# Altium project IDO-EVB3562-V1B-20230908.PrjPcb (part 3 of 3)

## Sheet P21. USB3.SchDoc
size 420 x 297 mm
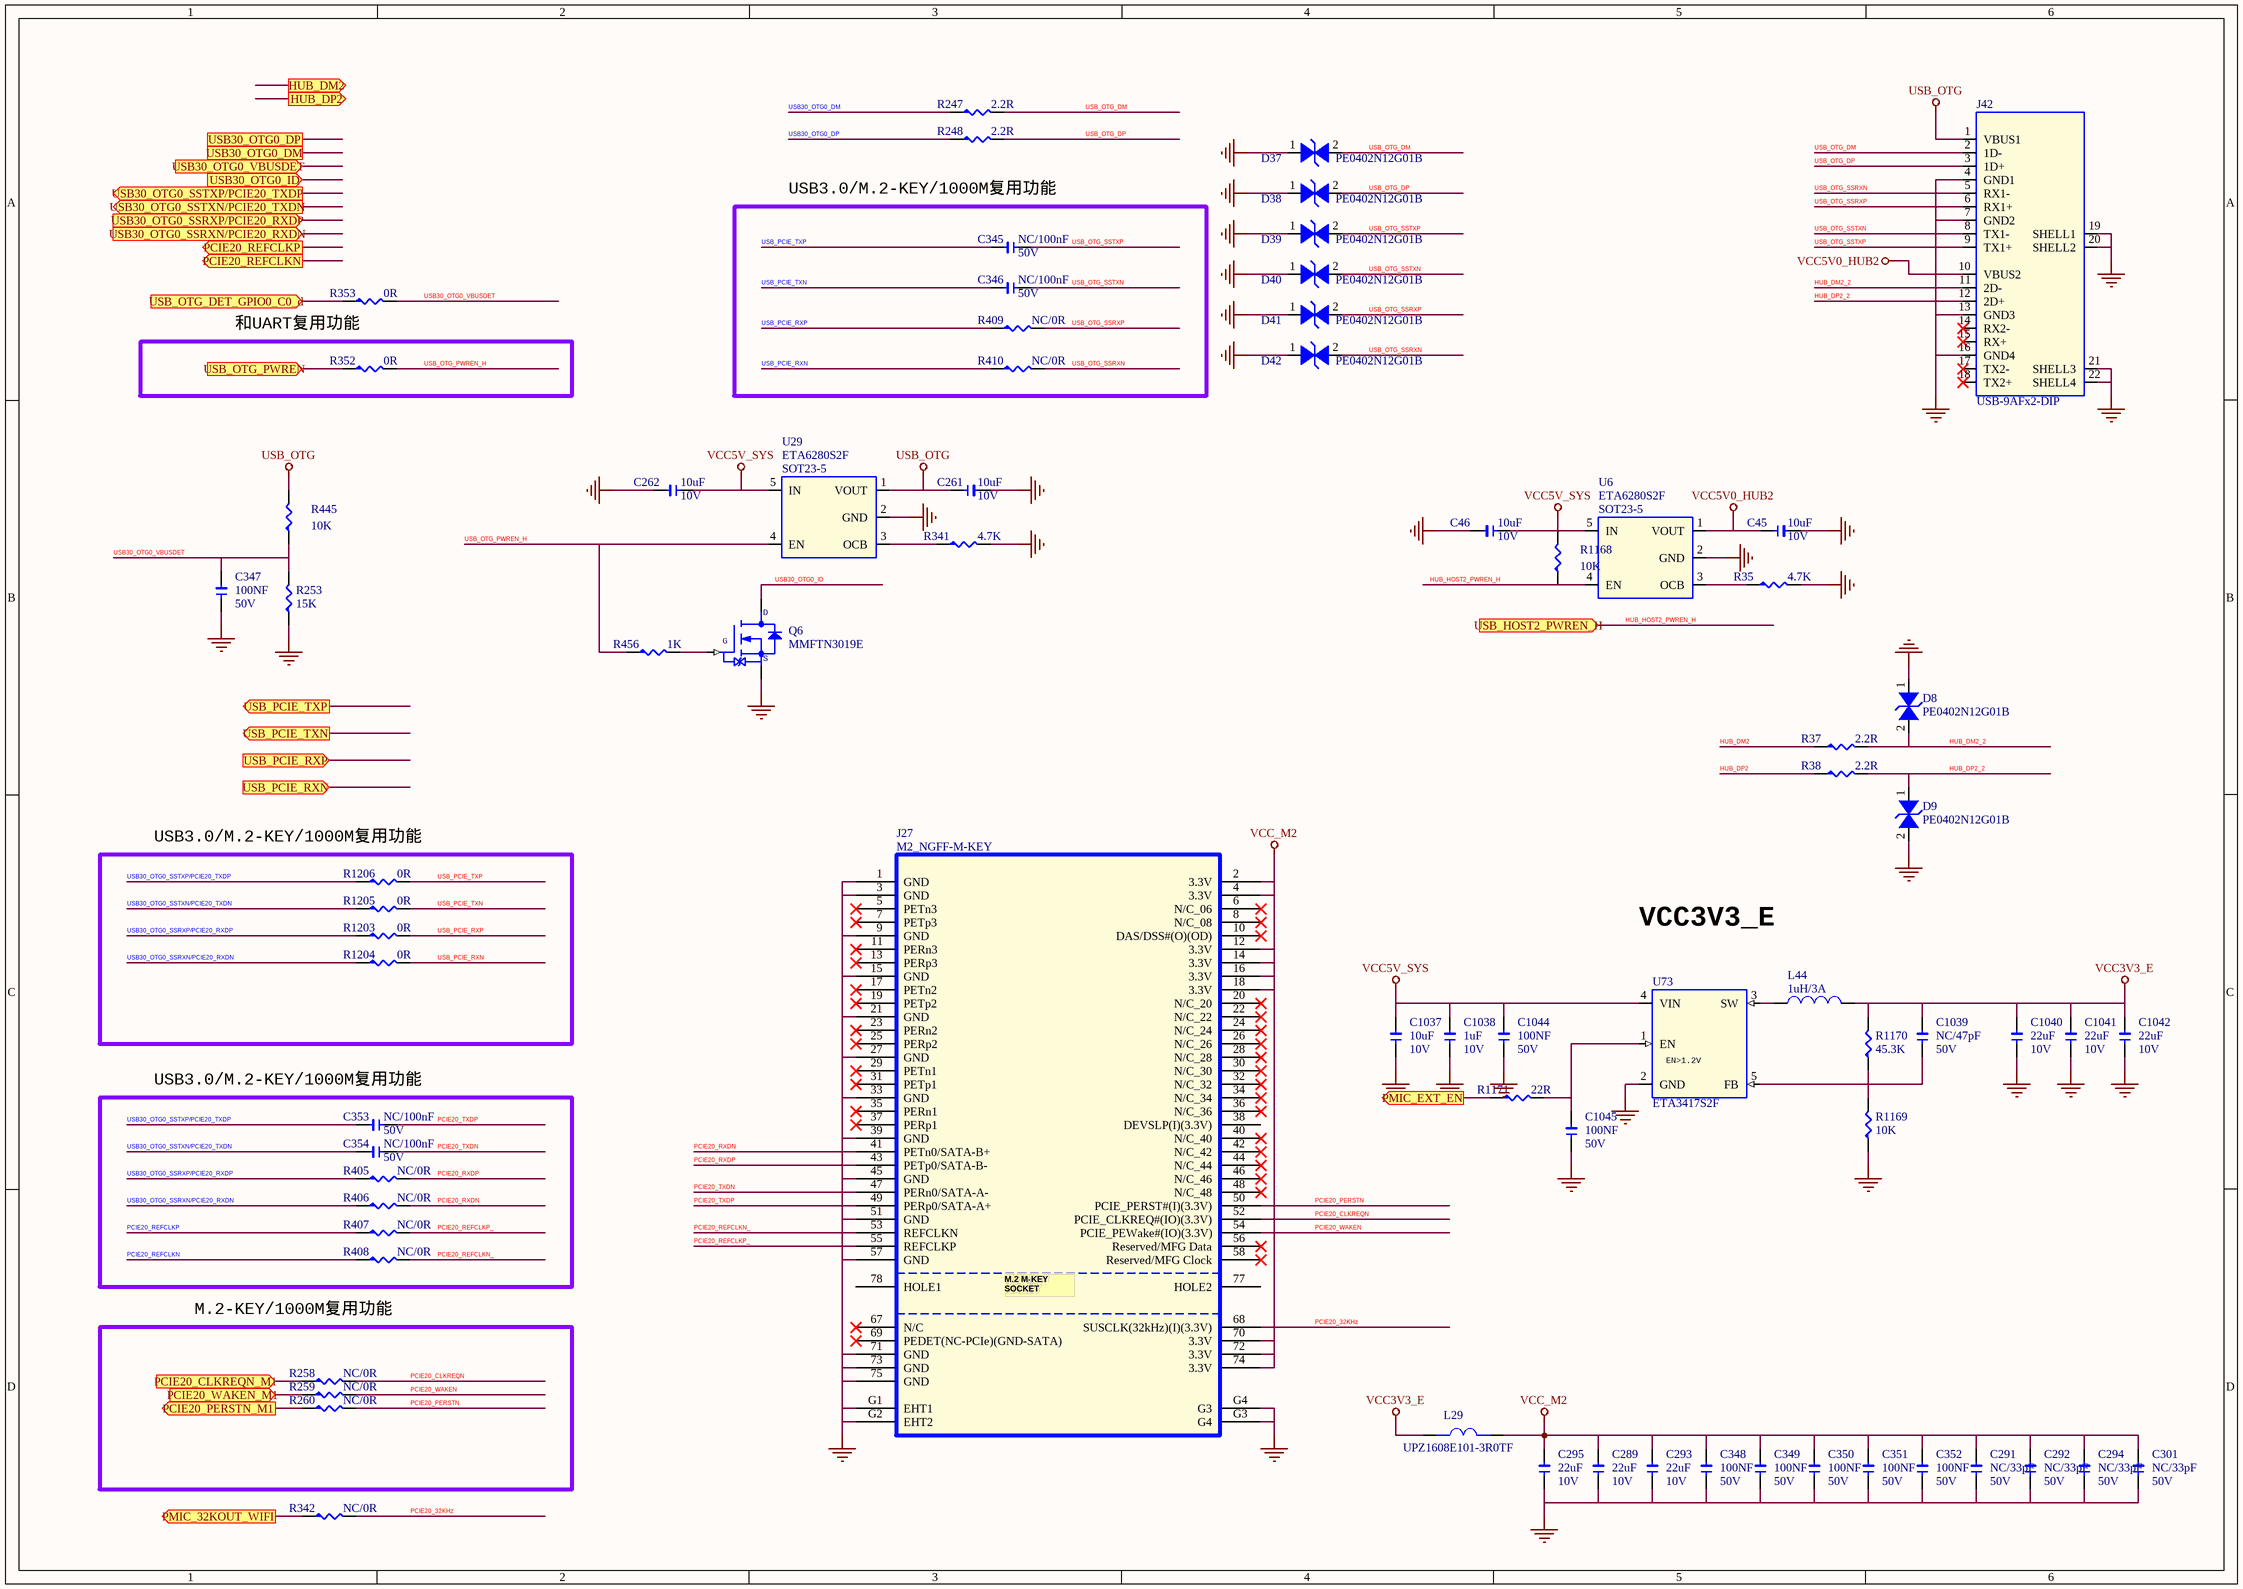
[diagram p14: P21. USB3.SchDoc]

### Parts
C45  10uF  DSC2: 10V  [1206]
C46  10uF  DSC2: 10V  [1206]
C261  10uF  DSC2: 10V  [1206]
C262  10uF  DSC2: 10V  [1206]
C289  22uF  DSC2: 10V  [1206]
C291  NC/33pF  DSC2: 50V  [1206]
C292  NC/33pF  DSC2: 50V  [1206]
C293  22uF  DSC2: 10V  [1206]
C294  NC/33pF  DSC2: 50V  [1206]
C295  22uF  DSC2: 10V  [1206]
C301  NC/33pF  DSC2: 50V  [1206]
C345  NC/100nF  DSC2: 50V  [1206]
C346  NC/100nF  DSC2: 50V  [1206]
C347  100NF  DSC2: 50V  [1206]
C348  100NF  DSC2: 50V  [1206]
C349  100NF  DSC2: 50V  [1206]
C350  100NF  DSC2: 50V  [1206]
C351  100NF  DSC2: 50V  [1206]
C352  100NF  DSC2: 50V  [1206]
C353  NC/100nF  DSC2: 50V  [1206]
C354  NC/100nF  DSC2: 50V  [1206]
C1037  10uF  DSC2: 10V  [1206]
C1038  1uF  DSC2: 10V  [1206]
C1039  NC/47pF  DSC2: 50V  [1206]
C1040  22uF  DSC2: 10V  [1206]
C1041  22uF  DSC2: 10V  [1206]
C1042  22uF  DSC2: 10V  [1206]
C1044  100NF  DSC2: 50V  [1206]
C1045  100NF  DSC2: 50V  [1206]
D8  PE0402N12G01B  [V0402]
D9  PE0402N12G01B  [V0402]
D37  PE0402N12G01B  [V0402]
D38  PE0402N12G01B  [V0402]
D39  PE0402N12G01B  [V0402]
D40  PE0402N12G01B  [V0402]
D41  PE0402N12G01B  [V0402]
D42  PE0402N12G01B  [V0402]
J27  M2_NGFF-M-KEY  [M2_NGFF-M-KEY]
J42  USB-9AFx2-DIP  [USB-9AF-DIP_2x]
L29  UPZ1608E101-3R0TF  [L0603]
L44  1uH/3A  [IND_252012]
Q6  MMFTN3019E  [SOT523]
R35  4.7K  [R0402]
R37  2.2R  [R0402]
R38  2.2R  [R0402]
R247  2.2R  [R0402]
R248  2.2R  [R0402]
R253  15K  [R0402]
R258  NC/0R  [R0402]
R259  NC/0R  [R0402]
R260  NC/0R  [R0402]
R341  4.7K  [R0402]
R342  NC/0R  [R0402]
R352  0R  [R0402]
R353  0R  [R0402]
R405  NC/0R  [R0402]
R406  NC/0R  [R0402]
R407  NC/0R  [R0402]
R408  NC/0R  [R0402]
R409  NC/0R  [R0402]
R410  NC/0R  [R0402]
R445  10K  [R0402]
R456  1K  [R0402]
R1168  10K  [R0402]
R1169  10K  [R0402]
R1170  45.3K  [R0402]
R1171  22R  [R0402]
R1203  0R  [R0402]
R1204  0R  [R0402]
R1205  0R  [R0402]
R1206  0R  [R0402]
U6  ETA6280S2F  [SOT23-5]
U29  ETA6280S2F  [SOT23-5]
U73  ETA3417S2F  [SOT23-5]

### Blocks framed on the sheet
USB3.0/M.2-KEY/1000M复用功能: C345 C346 R409 R410
和UART复用功能: R352
USB3.0/M.2-KEY/1000M复用功能: R1203-R1206
USB3.0/M.2-KEY/1000M复用功能: C353 C354 R405-R408
M.2-KEY/1000M复用功能: R258-R260

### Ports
HUB_DM2 (out), HUB_DP2 (out), PCIE20_CLKREQN_M1 (in), PCIE20_PERSTN_M1 (out), PCIE20_REFCLKN (out), PCIE20_REFCLKP (out), PCIE20_WAKEN_M1 (in), PMIC_32KOUT_WIFI (out), PMIC_EXT_EN (out), USB30_OTG0_DM, USB30_OTG0_DP, USB30_OTG0_ID (in), USB30_OTG0_SSRXN/PCIE20_RXDN (in), USB30_OTG0_SSRXP/PCIE20_RXDP (in), USB30_OTG0_SSTXN/PCIE20_TXDN (out), USB30_OTG0_SSTXP/PCIE20_TXDP (out), USB30_OTG0_VBUSDET (in), USB_HOST2_PWREN_H (in), USB_OTG_DET_GPIO0_C0_d (in), USB_OTG_PWREN (in), USB_PCIE_RXN (in), USB_PCIE_RXP (in), USB_PCIE_TXN (out), USB_PCIE_TXP (out)

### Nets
GND: C45.2 C46.2 C261.2 C262.2 C289.1 C291.1 C292.1 C293.1 C294.1 C295.1 C301.1 C347.1 C348.1 C349.1 C350.1 C351.1 C352.1 C1037.1 C1038.1 C1040.1 C1041.1 C1042.1 C1044.1 C1045.1 D8.1(I/O2) D9.2(I/O1) D37.1(I/O2) D38.1(I/O2) D39.1(I/O2) D40.1(I/O2) D41.1(I/O2) D42.1(I/O2) J27.1(GND) J27.3(GND) J27.9(GND) J27.15(GND) J27.21(GND) J27.27(GND) J27.33(GND) J27.39(GND) J27.45(GND) J27.51(GND) J27.57(GND) J27.71(GND) J27.73(GND) J27.75(GND) J27.G1(EHT1) J27.G2(EHT2) J27.G3(G4) J27.G4(G3) J42.4(GND1) J42.7(GND2) J42.13(GND3) J42.16(GND4) J42.19(SHELL1) J42.20(SHELL2) J42.21(SHELL3) J42.22(SHELL4) Q6.2(SOURCE) R35.2 R253.1 R341.2 R1169.1 U6.2(GND) U29.2(GND) U73.2(GND)
USB_OTG: C261.1 J42.1(VBUS1) R445.2 U29.1(VOUT)
VCC3V3_E: C1039.2 C1040.2 C1041.2 C1042.2 L29.1 L44.2 R1170.2
VCC5V0_HUB2: C45.1 J42.10(VBUS2) U6.1(VOUT)
VCC5V_SYS: C46.1 C262.1 C1037.2 C1038.2 C1044.2 R1168.2 U6.5(IN) U29.5(IN) U73.4(VIN)
VCC_M2: C289.2 C291.2 C292.2 C293.2 C294.2 C295.2 C301.2 C348.2 C349.2 C350.2 C351.2 C352.2 J27.2(3.3V) J27.4(3.3V) J27.12(3.3V) J27.14(3.3V) J27.16(3.3V) J27.18(3.3V) J27.70(3.3V) J27.72(3.3V) J27.74(3.3V) L29.2
HUB_DM2: R37.1
HUB_DM2_2: D8.2(I/O1) J42.11(2D-) R37.2
HUB_DP2: R38.1
HUB_DP2_2: D9.1(I/O2) J42.12(2D+) R38.2
HUB_HOST2_PWREN_H: R1168.1 U6.4(EN) ; port USB_HOST2_PWREN_H
PCIE20_32KHz: J27.68(SUSCLK(32kHz)(I)(3.3V)) R342.2
PCIE20_CLKREQN: J27.52(PCIE_CLKREQ#(IO)(3.3V)) R258.2
PCIE20_PERSTN: J27.50(PCIE_PERST#(I)(3.3V)) R260.2
PCIE20_REFCLKN: R408.1
PCIE20_REFCLKN_: J27.53(REFCLKN) R408.2
PCIE20_REFCLKP: R407.1
PCIE20_REFCLKP_: J27.55(REFCLKP) R407.2
PCIE20_RXDN: J27.41(PETn0/SATA-B+) R406.2
PCIE20_RXDP: J27.43(PETp0/SATA-B-) R405.2
PCIE20_TXDN: C354.1 J27.47(PERn0/SATA-A-)
PCIE20_TXDP: C353.1 J27.49(PERp0/SATA-A+)
PCIE20_WAKEN: J27.54(PCIE_PEWake#(IO)(3.3V)) R259.2
USB30_OTG0_DM: R247.1
USB30_OTG0_DP: R248.1
USB30_OTG0_ID: Q6.3(DRAIN)
USB30_OTG0_SSRXN/PCIE20_RXDN: R406.1 R1204.1
USB30_OTG0_SSRXP/PCIE20_RXDP: R405.1 R1203.1
USB30_OTG0_SSTXN/PCIE20_TXDN: C354.2 R1205.1
USB30_OTG0_SSTXP/PCIE20_TXDP: C353.2 R1206.1
USB30_OTG0_VBUSDET: C347.2 R253.2 R353.2 R445.1
USB_OTG_DM: D37.2(I/O1) J42.2(1D-) R247.2
USB_OTG_DP: D38.2(I/O1) J42.3(1D+) R248.2
USB_OTG_PWREN_H: R352.2 R456.1 U29.4(EN)
USB_OTG_SSRXN: D42.2(I/O1) J42.5(RX1-) R410.2
USB_OTG_SSRXP: D41.2(I/O1) J42.6(RX1+) R409.2
USB_OTG_SSTXN: C346.1 D40.2(I/O1) J42.8(TX1-)
USB_OTG_SSTXP: C345.1 D39.2(I/O1) J42.9(TX1+)
USB_PCIE_RXN: R410.1 R1204.2
USB_PCIE_RXP: R409.1 R1203.2
USB_PCIE_TXN: C346.2 R1205.2
USB_PCIE_TXP: C345.2 R1206.2
NetC1039_1: C1039.1 R1169.2 R1170.1 U73.5(FB)
NetC1045_2: C1045.2 R1171.2 U73.1(EN)
NetL44_1: L44.1 U73.3(SW)
NetM1_8: R1171.1 ; port PMIC_EXT_EN
NetM1_16: R342.1 ; port PMIC_32KOUT_WIFI
NetM1_72: R258.1 ; port PCIE20_CLKREQN_M1
NetM1_73: R259.1 ; port PCIE20_WAKEN_M1
NetM1_74: R260.1 ; port PCIE20_PERSTN_M1
NetM1_158: R353.1 ; port USB_OTG_DET_GPIO0_C0_d
NetQ6_1: Q6.1(GATE) R456.2
NetR35_1: R35.1 U6.3(OCB)
NetR341_1: R341.1 U29.3(OCB)
NetR352_1: R352.1 ; port USB_OTG_PWREN

Not connected (* = marked no-connect by the designer): J27 5(PETn3)* 6(N/C_06)* 7(PETp3)* 8(N/C_08)* 10(DAS/DSS#(O)(OD))* 11(PERn3)* 13(PERp3)* 17(PETn2)* 19(PETp2)* 20(N/C_20)* 22(N/C_22)* 23(PERn2)* 24(N/C_24)* 25(PERp2)* 26(N/C_26)* 28(N/C_28)* 29(PETn1)* 30(N/C_30)* 31(PETp1)* 32(N/C_32)* 34(N/C_34)* 35(PERn1)* 36(N/C_36)* 37(PERp1)* 38(DEVSLP(I)(3.3V)) 40(N/C_40)* 42(N/C_42)* 44(N/C_44)* 46(N/C_46)* 48(N/C_48)* 56(Reserved/MFG_Data)* 58(Reserved/MFG_Clock)* 67(N/C)* 69(PEDET(NC-PCIe)(GND-SATA))* 77(HOLE2) 78(HOLE1); J42 14(RX2-)* 15(RX+)* 17(TX2-)* 18(TX2+)*

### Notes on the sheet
- VCC3V3_E
- (near U73) EN>1.2V

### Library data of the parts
C45 = C-0603: Manufacture: 三星¦国巨¦村田; Part Name: 贴片电容; Part Number: C020102120071; PCB Footprint: C0603; ID: 71; DSC3: X5R; DSC1: ±20%; ERP Number: 1010200076
C46 = C-0603: Part Number: C020102120071; Part Name: 贴片电容; Manufacture: 三星¦国巨¦村田; ERP Number: 1010200076; DSC1: ±20%; DSC3: X5R; ID: 71; PCB Footprint: C0603
C261 = C-0603: Part Number: C020102120071; Part Name: 贴片电容; Manufacture: 三星¦国巨¦村田; PCB Footprint: C0603; ERP Number: 1010200076; DSC1: ±20%; DSC3: X5R; ID: 71
C262 C1037 = C-0603: Manufacture: 三星¦国巨¦村田; Part Name: 贴片电容; Part Number: C020102120071; ID: 71; DSC3: X5R; DSC1: ±20%; ERP Number: 1010200076; PCB Footprint: C0603
C289 C293 C295 = C-0603: Part Number: C020107143899; Part Name: 贴片电容; Manufacture: 三星¦国巨¦村田; PCB Footprint: C0603; DSC1: ±20%; DSC3: X5R; ID: 83
C291 C292 C294 C301 = C-0402_Dup1: Manufacture: 三星¦国巨¦村田; Part Name: 贴片电容; Part Number: C020102120033; ID: 33; DSC3: C0G; DSC1: ±5%; ERP Number: 1010200087; PCB Footprint: C0402
C345 C346 C353 = C-0402: Manufacture: 三星¦国巨¦村田; Part Name: 贴片电容; Part Number: C020102120061; ID: 61; DSC3: X7R; DSC1: ±10%; ERP Number: 1010200128; PCB Footprint: C0402
C347 C1044 C1045 = C-0402_Dup2: Part Number: C020102120061; Part Name: 贴片电容; Manufacture: 三星¦国巨¦村田; ERP Number: 1010200128; DSC1: ±10%; DSC3: X7R; ID: 61; PCB Footprint: C0402
C348-C352 = C-0402_Dup2: Manufacture: 三星¦国巨¦村田; Part Name: 贴片电容; Part Number: C020102120061; ID: 61; DSC3: X7R; DSC1: ±10%; ERP Number: 1010200128; PCB Footprint: C0402
C354 = C-0402: Part Number: C020102120061; Part Name: 贴片电容; Manufacture: 三星¦国巨¦村田; ERP Number: 1010200128; DSC1: ±10%; DSC3: X7R; ID: 61; PCB Footprint: C0402
C1038 = C-0402_Dup1: Part Number: C020102120064; Part Name: 贴片电容; Manufacture: 三星¦国巨¦村田; ERP Number: 1010200054; DSC1: ±10%; DSC3: X5R; ID: 64; PCB Footprint: C0402
C1039 = C-0402_Dup1: Part Number: C020102120036; Part Name: 贴片电容; Manufacture: 三星¦国巨¦村田; ERP Number: 1010200213; DSC1: ±5%; DSC3: C0G; ID: 36; PCB Footprint: C0402
C1040-C1042 = C-0603: Part Number: C020107143899; Part Name: 贴片电容; Manufacture: 三星¦国巨¦村田; DSC1: ±20%; DSC3: X5R; ID: 83; PCB Footprint: C0603
D8 = DI-ESD: ESD 0402; Part Number: C040504013980; Manufacture P/N: MLVG04021R0UV18; Manufacturer: INPAQ; Manufacture: 硕凯; PN Type: Varistor; DSC1: 双向; DSC2: Vdc=12V; DSC4: Vc=40V; DSC5: Cj=0.05pF; ID: 1; Solder: 推荐
D9 D37-D42 = DI-ESD: ESD 0402; Part Number: C040504013980; Manufacture P/N: MLVG04021R0UV18; Manufacturer: INPAQ; Manufacture: 硕凯; PN Type: Varistor; Solder: 推荐; ID: 1; DSC5: Cj=0.05pF; DSC4: Vc=40V; DSC2: Vdc=12V; DSC1: 双向
J27 = J-M2_NGFF-M-KEY_1: Part Number: J050105094667; Part Name: 金手指连接器; DSC1: M2_NGFF-M座子,0.5mm Pitch,H=4.2mm; DSC2: 67P; DSC3: 贴片; DSC4: 91302-42-067RDM(Umaxconn); ID: 28
J42 = J-USB-9AFx2-DIP-W: USB,TYPE-A,2PORT,R/A,W/SHIELD; Part Number: J060111093946; Part Name: USB连接器; VSTNO: H00025; DSC1: USB-3.0，插件弯脚，双层，蓝胶，有卷边，耐高温; DSC2: 17.5*14.5*15.5mm; DSC3: 通孔弯针; DSC5: JLX-USB-030（九龙熹）; ID: 14
L29 = FB-0603_Dup1: SMD Multilayer Ferrite Chip Bead,3A,30Ohm,0.03R; Manufacturer: SUNLORD; Manufacture2 P/N: PBY160808T-400Y-N; Manufacture P/N: PZ1608D300-3R0TF; Part Number: C060502370005; Part Name: 贴片磁珠; Manufacture: 顺络; PN Type: SMD FERRITE BEAD; ERP Number: 1010200207; DSC1: 100Ω@100MHz; DSC3: DCR=30mΩ; DSC4: 电源线; ID: 5
L44 = L-IND_Dup1: Manufacture: 宗成¦长江微电¦顺络; Part Name: 功率电感; ID: 52; DSC8: ZCRH252012-1uH-M(宗成); DSC7: FHD252012S-1R0MT(长江微电); DSC6: WPN252012H1R0MT(顺络); DSC5: 2.5*2.0*1.2mm; DSC4: 54mΩ; DSC3: Irms=3A; DSC2: Isat=3.6A; DSC1: ±20%
Q6 = N-MOS-Q: Part Number: C030202190004; Part Name: N-MOS; Manufacture: 先科; ERP Number: 1010800011; DSC1: Vds=30V; DSC2: Id=100mA; DSC3: Vgs(th)=1.5V; DSC4: Vgs=±20V; DSC5: pd=150mW; ID: 4
R35 R341 = R-0402_Dup3: Part Number: C011002080320; Part Name: 贴片电阻; ID: 320; DSC2: 1/16W; DSC1: ±5%; ERP Number: 1010200177
R37 R38 = R-0402_Dup3: Part Name: 贴片电阻; Part Number: C011002080238; ERP Number: 1010200263; DSC1: ±5%; DSC2: 1/16W; ID: 238
R247 R248 = R-0402_Dup3: Part Number: C011002080238; Part Name: 贴片电阻; ID: 238; DSC2: 1/16W; DSC1: ±5%; ERP Number: 1010200263
R253 = R-0402_Dup3: Part Name: 贴片电阻; Part Number: C011002080332; ERP Number: 1010200258; DSC1: ±5%; DSC2: 1/16W; ID: 332
R258-R260 R342 R353 R405-R410 R1203 R1205 R1206 = R-0402_Dup3: Part Number: C011002080413; Part Name: 贴片电阻; ID: 413; DSC2: 1/16W; DSC1: ±1%
R352 R1204 = R-0402_Dup3: Part Name: 贴片电阻; Part Number: C011002080413; DSC1: ±1%; DSC2: 1/16W; ID: 413
R445 R1168 R1169 = R-0402_Dup3: Part Number: C011002080856; Part Name: 贴片电阻; ID: 856; DSC2: 1/16W; DSC1: ±1%; ERP Number: 1010200140
R456 = R-0402_Dup3: Part Name: 贴片电阻; Part Number: C011002080742; ERP Number: 1010200113; DSC1: ±1%; DSC2: 1/16W; ID: 742
R1170 = R-0402_Dup3: Part Name: 贴片电阻; Part Number: C011002080933; DSC1: ±1%; DSC2: 1/16W; ID: 933
R1171 = R-0402_Dup3: Part Number: C011002080262; Part Name: 贴片电阻; ID: 262; DSC2: 1/16W; DSC1: ±5%; ERP Number: 1010200173
U6 = U-SY6280AAC: Part Name: 功率开关; Manufacture: ETA; DSC1: 低能耗电源开关; DSC2: 2.4-5.5V 2A; DSC3: 80mA; DSC4: -40~85℃; ID: 1
U29 = U-SY6280AAC: Manufacture: ETA; Part Name: 功率开关; ID: 1; DSC4: -40~85℃; DSC3: 80mA; DSC2: 2.4-5.5V 2A; DSC1: 低能耗电源开关
U73 = U-ETA3417S2F: Part Name: DCDC; Part Number: C070205183984; Manufacture: ETA; DSC1: Vi=2.6-7.0V; DSC2: Vo=0.6-7.0V; DSC3: Io=2.5A; DSC4: Vfb=0.6V; DSC6: 3MHz; DSC7: 同步降压; DSC8: 替代料：TI的TLV62569DBVR/矽力杰SY8089AAAC; Solder: 量产; ID: 43

## Sheet P22.SchDoc
size 297 x 209 mm
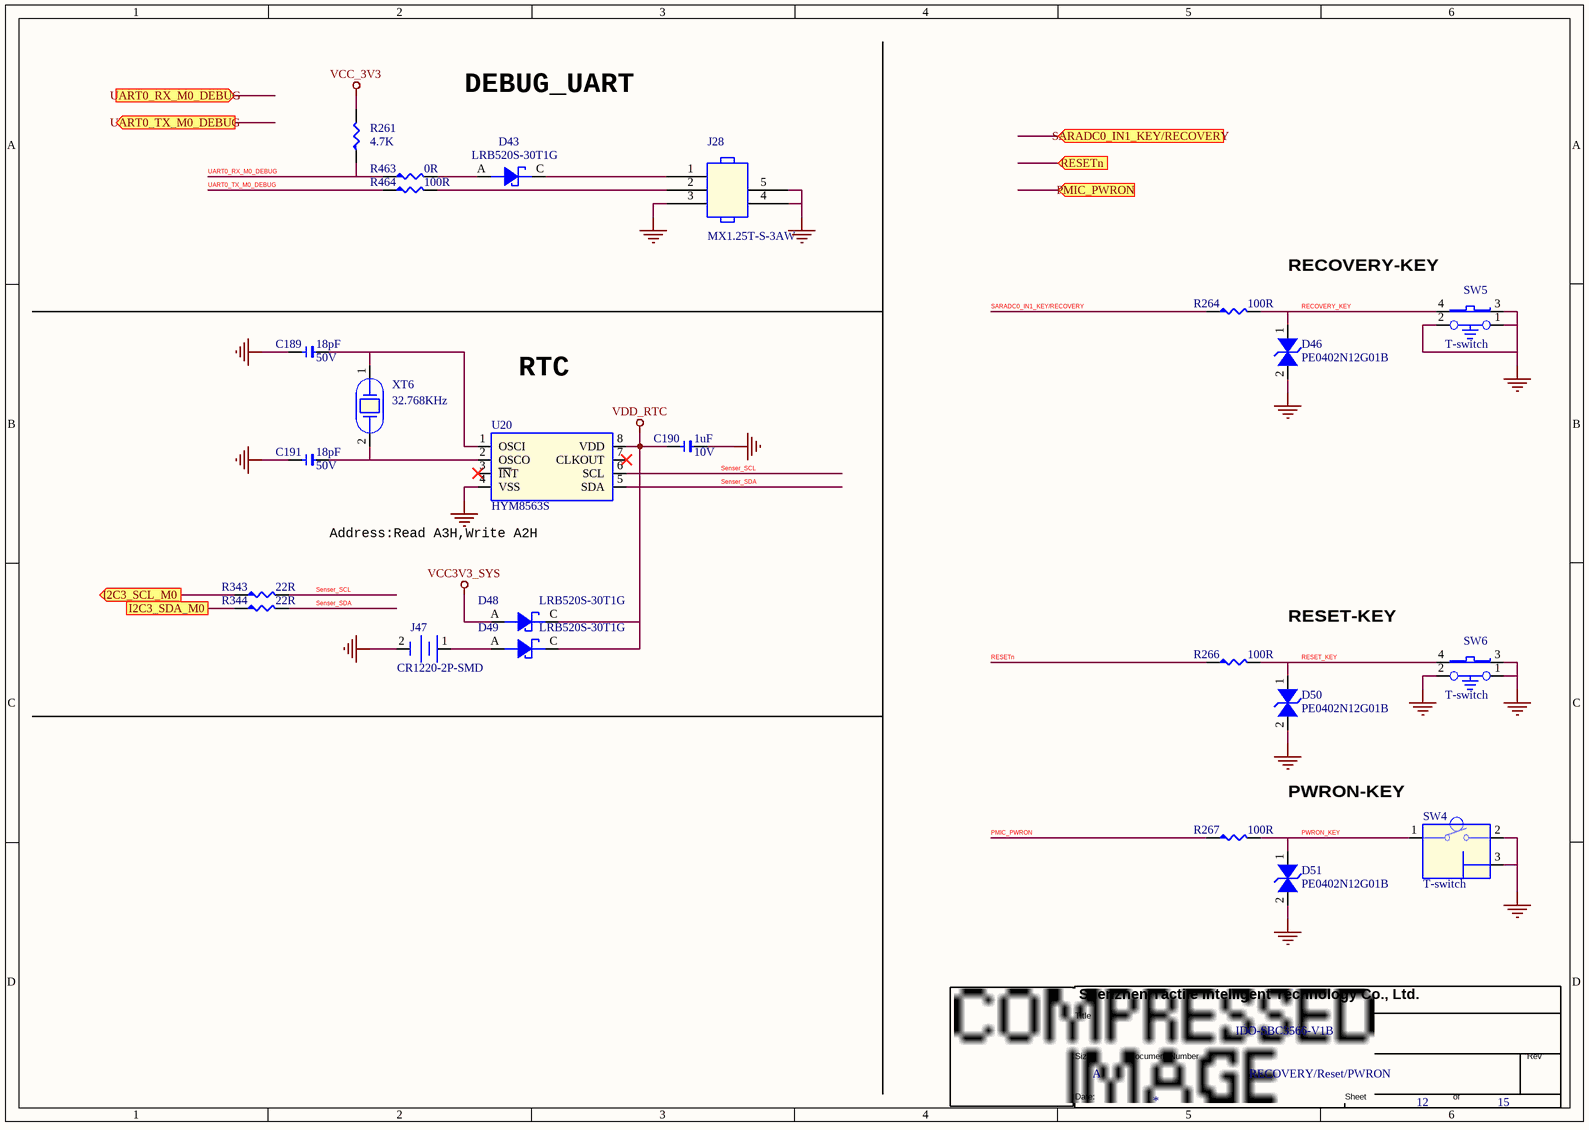
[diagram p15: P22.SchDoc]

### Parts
(Parts that share a designator on the sheet are numbered #1, #2 ... from top to bottom, then left to right.)
*#9  Page Count: 15  Page Number: 12  Page Size: A  Title: IDO-SBC3566-V1B  Doc: RECOVERY/Reset/PWRON  (hidden comment: TitleBlock1)  (graphical)
C189  18pF  DSC2: 50V  [1206]
C190  1uF  DSC2: 10V  [1206]
C191  18pF  DSC2: 50V  [1206]
D43  LRB520S-30T1G  [SOD523]
D46  PE0402N12G01B  [V0402]
D48  LRB520S-30T1G  [SOD523]
D49  LRB520S-30T1G  [SOD523]
D50  PE0402N12G01B  [V0402]
D51  PE0402N12G01B  [V0402]
J28  MX1.25T-S-3AW  [MX125T-S-3AW]
J47  CR1220-2P-SMD  [CR1220-2P-SMD]
R261  4.7K  [R0402]
R264  100R  [R0402]
R266  100R  [R0402]
R267  100R  [R0402]
R343  22R  [R0402]
R344  22R  [R0402]
R463  0R  [R0402]
R464  100R  [R0402]
SW4  T-switch  [PB-SIDE-P-4_5x4_5]
SW5  T-switch  [PB-SIDE-S-3_5x4_5]
SW6  T-switch  [PB-SIDE-S-3_5x4_5]
U20  HYM8563S  [MSOP-8]
XT6  32.768KHz  [XTAL_32X15_2P]

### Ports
I2C3_SCL_M0 (out), I2C3_SDA_M0, PMIC_PWRON (in), RESETn (in), SARADC0_IN1_KEY/RECOVERY (in), UART0_RX_M0_DEBUG (in), UART0_TX_M0_DEBUG (out)

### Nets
GND: C189.1 C190.2 C191.1 D46.2(I/O1) D50.2(I/O1) D51.2(I/O1) J28.3 J28.4 J28.5 J47.2 SW4.2 SW4.3 SW5.1 SW5.2 SW5.3 SW6.1 SW6.2 SW6.3 U20.4(VSS)
VCC3V3_SYS: D48.A
VCC_3V3: R261.2
VDD_RTC: C190.1 D48.C D49.C U20.8(VDD)
PMIC_PWRON: R267.1
PWRON_KEY: D51.1(I/O2) R267.2 SW4.1
RECOVERY_KEY: D46.1(I/O2) R264.2 SW5.4
RESET_KEY: D50.1(I/O2) R266.2 SW6.4
RESETn: R266.1
SARADC0_IN1_KEY/RECOVERY: R264.1
SCL_TP: R343.1 ; port I2C3_SCL_M0
SDA_TP: R344.1 ; port I2C3_SDA_M0
Senser_SCL: R343.2 U20.6(SCL)
Senser_SDA: R344.2 U20.5(SDA)
UART0_RX_M0_DEBUG: R261.1 R463.1
UART0_TX_M0_DEBUG: R464.1
NetC189_2: C189.2 U20.1(OSCI) XT6.1
NetC191_2: C191.2 U20.2(OSCO) XT6.2
NetD43_A: D43.A R463.2
NetD43_C: D43.C J28.1
NetD49_A: D49.A J47.1
NetJ28_2: J28.2 R464.2

Not connected (* = marked no-connect by the designer): U20 3(~{IN}T)* 7(CLKOUT)*

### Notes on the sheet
- DEBUG_UART
- RECOVERY-KEY
- RTC
- (near U20) Address:Read A3H,Write A2H
- RESET-KEY
- PWRON-KEY

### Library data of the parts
C189 C191 = C-0402_Dup1: Manufacture: 三星¦国巨¦村田; Part Name: 贴片电容; Part Number: C020102120027; ID: 27; DSC3: C0G; DSC1: ±5%; ERP Number: 1010200091; PCB Footprint: C0402
C190 = C-0402_Dup1: Part Number: C020102120064; Part Name: 贴片电容; Manufacture: 三星¦国巨¦村田; PCB Footprint: C0402; ERP Number: 1010200054; DSC1: ±10%; DSC3: X5R; ID: 64
D43 = DI-XI-S_Dup1: Part Number: C040202220002; Part Name: 肖特基二级管; Manufacture: 乐山无线电; CLASS: IC; DSC1: VR=30V; DSC2: IF=200mA; DSC3: VF=350mV/10mA; DSC4: IR=0.5uA; ID: 2; Solder: 推荐
D46 = DI-ESD: as D9 on sheet P21. USB3
D48 D49 = DI-XI-S_Dup1: Manufacture: 乐山无线电; Part Name: 肖特基二级管; Part Number: C040202220002; CLASS: IC; Solder: 推荐; ID: 2; DSC4: IR=0.5uA; DSC3: VF=350mV/10mA; DSC2: IF=200mA; DSC1: VR=30V
D50 D51 = DI-ESD: as D8 on sheet P21. USB3
J28 = J-A-3P: Part Number: J020102800040; ID: 2; DSC6: X9821WRS-03-9TSN(星坤); DSC5: JLX-1.25T-3AWB(九龙熹); DSC4: 米黄色胶壳 耐高温; DSC3: 卧贴; DSC2: 1.25mm间距; DSC1: 3p
J47 = RTC-VBAT-2P: Part Name: 电池座; Part Number: J100303030001; ID: 4; DSC4: JLX-CR1220-2T（九龙熹）; DSC3: 贴片; DSC2: 19.3*14.2*4.1mm; DSC1: CR1220电池适用，贴片，双定位柱; ERP Number: 1040100045
R261 = R-0402_Dup3: Part Name: 贴片电阻; Part Number: C011002080818; ERP Number: 1010200445; DSC1: ±1%; DSC2: 1/16W; ID: 818
R264 R464 = R-0402_Dup3: Part Name: 贴片电阻; Part Number: C011002080279; ERP Number: 1010200160; DSC1: ±5%; DSC2: 1/16W; ID: 279
R266 R267 = R-0402_Dup3: Part Number: C011002080279; Part Name: 贴片电阻; ID: 279; DSC2: 1/16W; DSC1: ±5%; ERP Number: 1010200160
R343 = R-0402_Dup3: as R1171 on sheet P21. USB3
R344 = R-0402_Dup3: Part Name: 贴片电阻; Part Number: C011002080262; ERP Number: 1010200173; DSC1: ±5%; DSC2: 1/16W; ID: 262
R463 = R-0402_Dup3: as R258-R260 on sheet P21. USB3
SW4 = SW-3P: Part Number: C180104013837; Part Name: 轻触开关; DSC1: 轻触开关 带支架侧键 插件 柄长4.8mm; DSC2: DIP,4.5*4.5mm*4.8mm; DSC3: K2-1109DE-C4SW-01(韩荣); ID: 9
SW5 SW6 = SW-TS24CA: Part Number: C180102690004; Part Name: 轻触开关; DSC1: 轻触开关 侧键 贴片 带定位柱; DSC2: SMD,3.5*4.5mm; DSC3: TS24CA(首韩); ID: 4
U20 = U-HYM8563S: Manufacture: HAOYU(昊昱); Part Name: RTC芯片; Part Number: C110204273853; ID: 16; DSC3: -40℃~+85℃; DSC2: TSSOP8; DSC1: RTC,I2C, VCC=2.0-5.5V
XT6 = XTAL-2P: Part Name: 贴片无源晶振; Part Number: C050102290002; Manufacture: 泰晶; CLASS: IC; DSC1: 70kΩ; DSC2: ±20ppm; DSC3: 12.5pF; DSC4: -40℃~+85℃; DSC5: 3.2*1.5mm 2P; ID: 2

## Sheet P24.SchDoc
size 420 x 297 mm
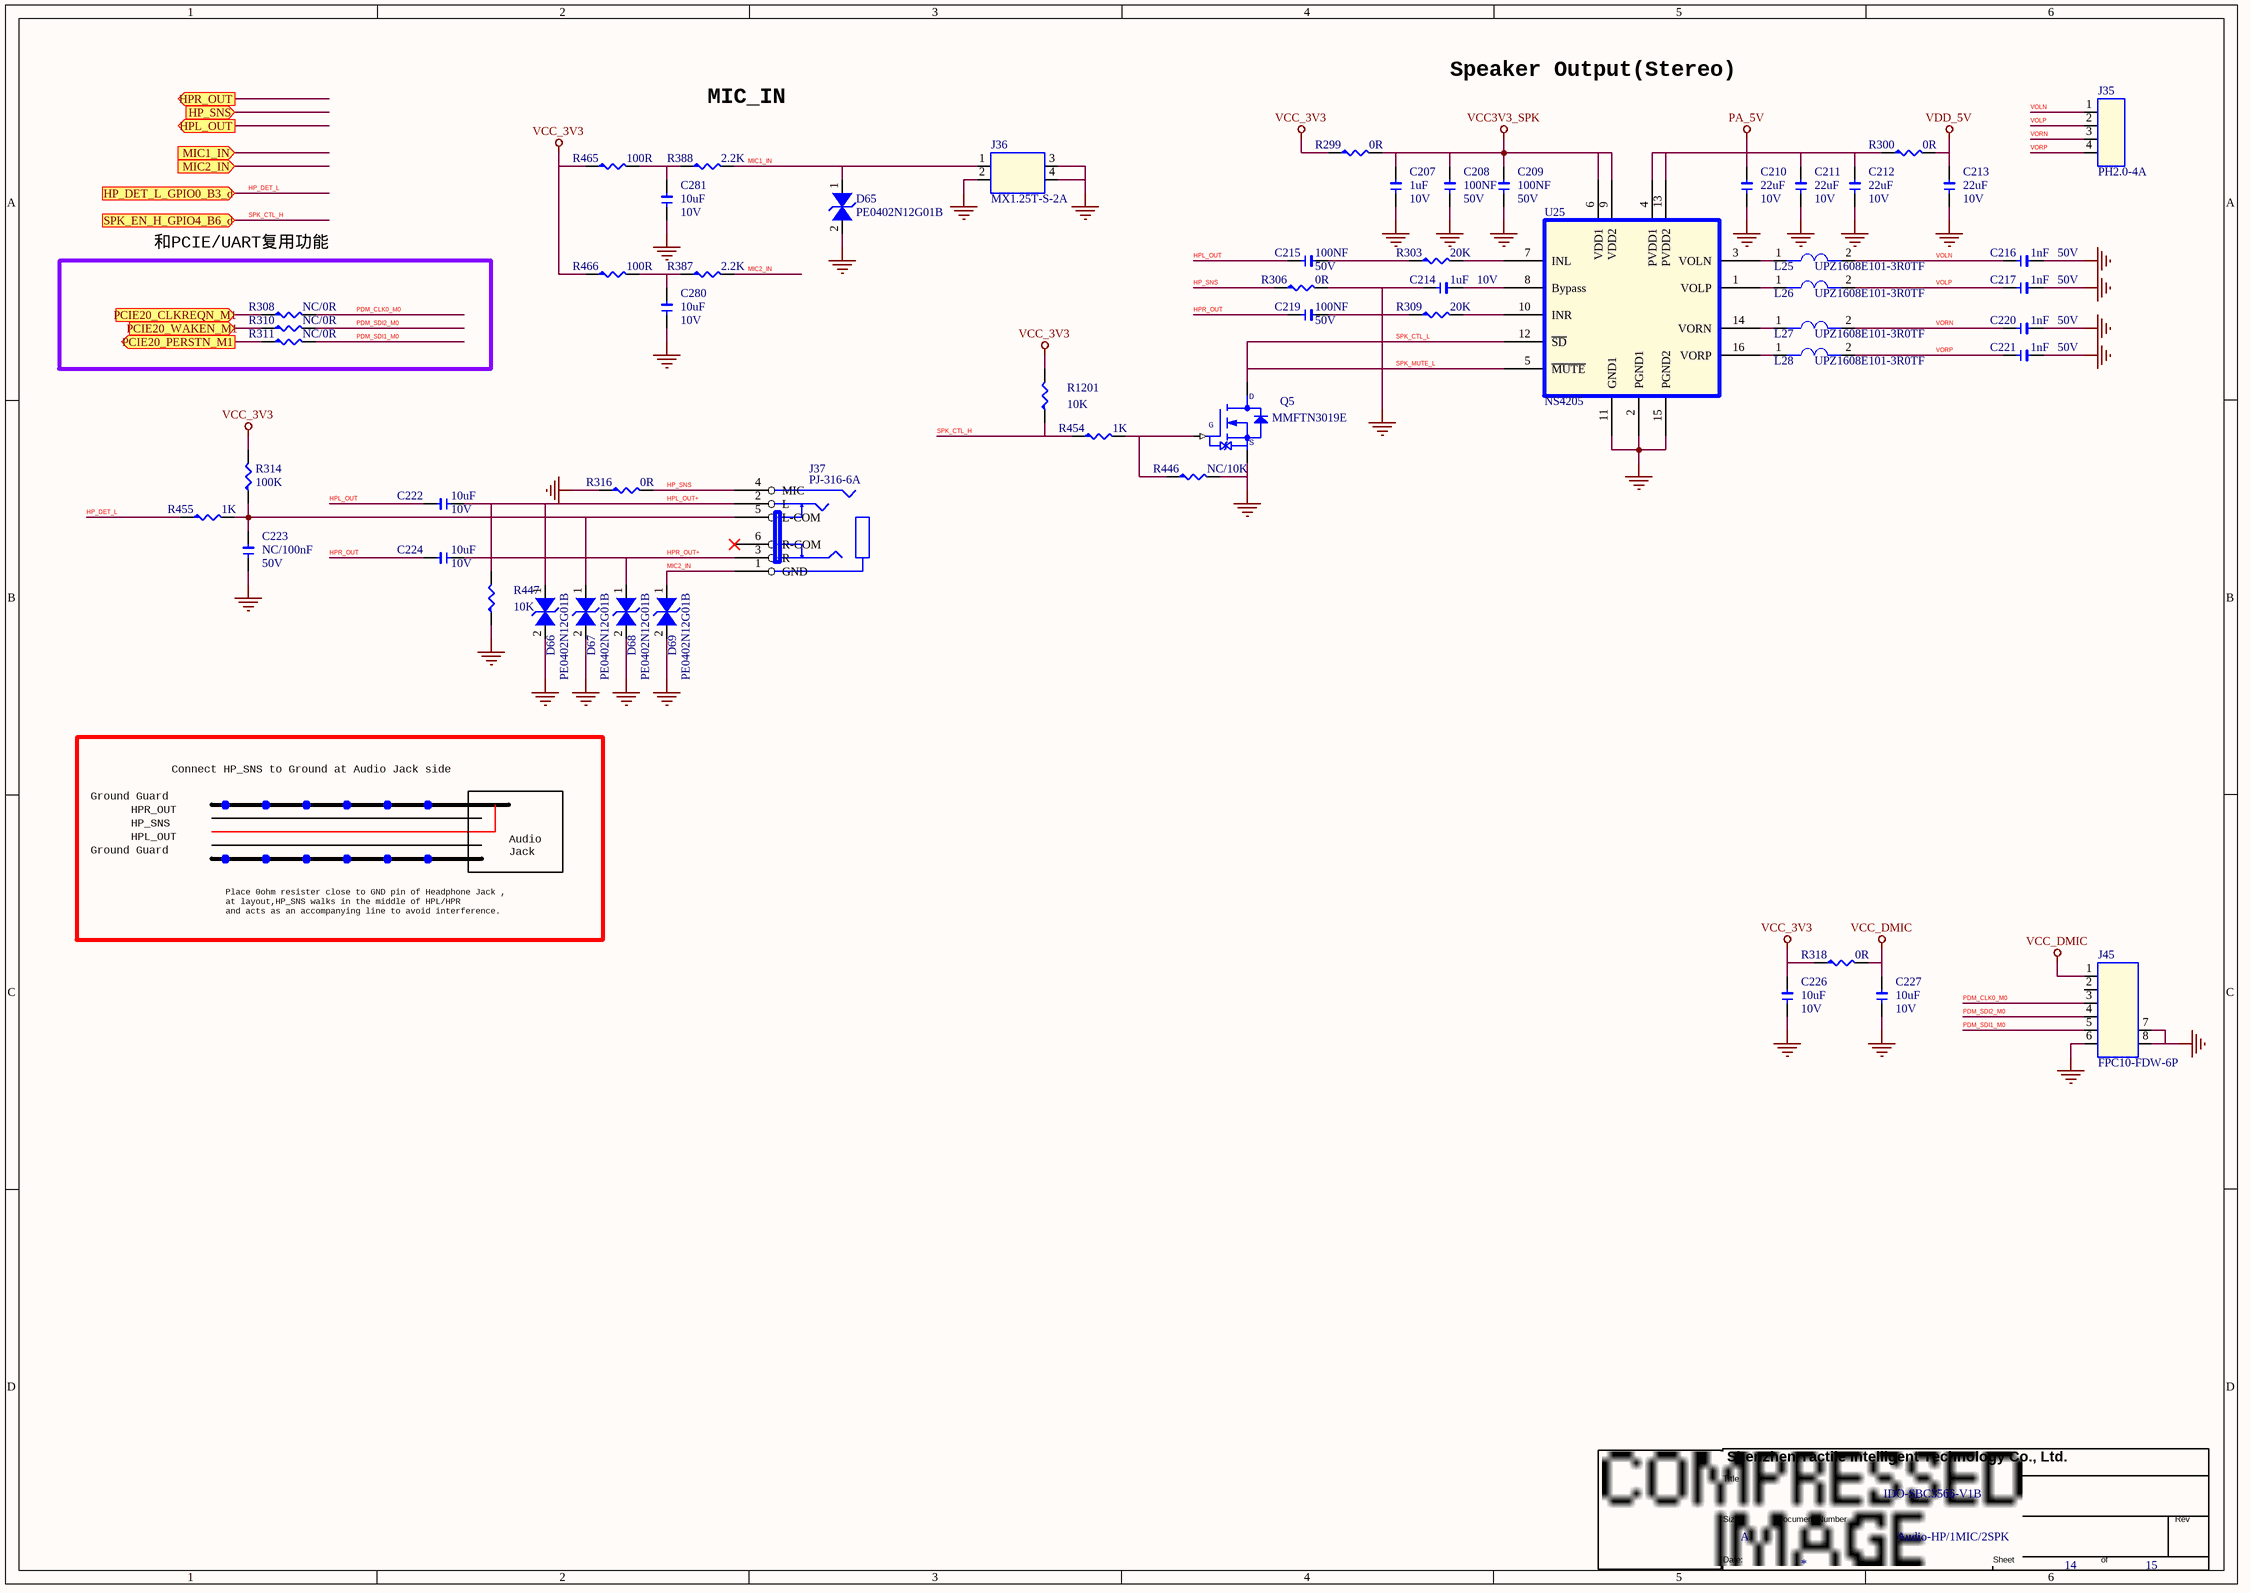
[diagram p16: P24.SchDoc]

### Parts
(Parts that share a designator on the sheet are numbered #1, #2 ... from top to bottom, then left to right.)
*#10  Page Count: 15  Page Number: 14  Page Size: A  Title: IDO-SBC3566-V1B  Doc: Audio-HP/1MIC/2SPK  (hidden comment: TitleBlock1)  (graphical)
C207  1uF  DSC2: 10V  [1206]
C208  100NF  DSC2: 50V  [1206]
C209  100NF  DSC2: 50V  [1206]
C210  22uF  DSC2: 10V  [1206]
C211  22uF  DSC2: 10V  [1206]
C212  22uF  DSC2: 10V  [1206]
C213  22uF  DSC2: 10V  [1206]
C214  1uF  DSC2: 10V  [1206]
C215  100NF  DSC2: 50V  [1206]
C216  1nF  DSC2: 50V  [1206]
C217  1nF  DSC2: 50V  [1206]
C219  100NF  DSC2: 50V  [1206]
C220  1nF  DSC2: 50V  [1206]
C221  1nF  DSC2: 50V  [1206]
C222  10uF  DSC2: 10V  [1206]
C223  NC/100nF  DSC2: 50V  [1206]
C224  10uF  DSC2: 10V  [1206]
C226  10uF  DSC2: 10V  [1206]
C227  10uF  DSC2: 10V  [1206]
C280  10uF  DSC2: 10V  [1206]
C281  10uF  DSC2: 10V  [1206]
D65  PE0402N12G01B  [V0402]
D66  PE0402N12G01B  [V0402]
D67  PE0402N12G01B  [V0402]
D68  PE0402N12G01B  [V0402]
D69  PE0402N12G01B  [V0402]
J35  PH2.0-4A  [PH200-4A]
J36  MX1.25T-S-2A  [MX125T-S-2A]
J37  PJ-316-6A  [PJ-316A-6A]
J45  FPC10-FDW-6P  [FPC10-6P]
L25  UPZ1608E101-3R0TF  [L0603]
L26  UPZ1608E101-3R0TF  [L0603]
L27  UPZ1608E101-3R0TF  [L0603]
L28  UPZ1608E101-3R0TF  [L0603]
Q5  MMFTN3019E  [SOT523]
R299  0R  [R0603]
R300  0R  [R0603]
R303  20K  [R0402]
R306  0R  [R0402]
R308  NC/0R  [R0402]
R309  20K  [R0402]
R310  NC/0R  [R0402]
R311  NC/0R  [R0402]
R314  100K  [R0402]
R316  0R  [R0402]
R318  0R  [R0603]
R387  2.2K  [R0402]
R388  2.2K  [R0402]
R446  NC/10K  [R0402]
R447  10K  [R0402]
R454  1K  [R0402]
R455  1K  [R0402]
R465  100R  [R0402]
R466  100R  [R0402]
R1201  10K  [R0402]
U25  NS4205  [SOP16-P127-390X990]

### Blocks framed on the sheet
和PCIE/UART复用功能: R308 R310 R311

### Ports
HP_DET_L_GPIO0_B3_d (in), HP_SNS (in), HPL_OUT (out), HPR_OUT (out), MIC1_IN (in), MIC2_IN (in), PCIE20_CLKREQN_M1 (in), PCIE20_PERSTN_M1 (out), PCIE20_WAKEN_M1 (in), SPK_EN_H_GPIO4_B6_d (in)

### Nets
GND: C207.1 C208.1 C209.1 C210.1 C211.1 C212.1 C213.1 C214.1 C216.2 C217.2 C220.2 C221.2 C223.1 C226.1 C227.1 C280.1 C281.1 D65.2(I/O1) D66.2(I/O1) D67.2(I/O1) D68.2(I/O1) D69.2(I/O1) J36.2 J36.3 J36.4 J45.6 J45.7 J45.8 Q5.2(SOURCE) R306.2 R316.1 R446.2 R447.1 U25.2(PGND1) U25.11(GND1) U25.15(PGND2)
PA_5V: C210.2 C211.2 C212.2 R300.1 U25.4(PVDD1) U25.13(PVDD2)
VCC3V3_SPK: C207.2 C208.2 C209.2 R299.2 U25.6(VDD1) U25.9(VDD2)
VCC_3V3: C226.2 R299.1 R314.2 R318.1 R465.1 R466.1 R1201.2
VCC_DMIC: C227.2 J45.1 R318.2
VDD_5V: C213.2 R300.2
HP_DET_L: R455.1 ; port HP_DET_L_GPIO0_B3_d
HP_SNS: J37.4(MIC) R306.1 R316.2
HPL_OUT: C215.1 C222.2
HPL_OUT+: C222.1 D66.1(I/O2) J37.2(L) R447.2
HPR_OUT: C219.1 C224.2
HPR_OUT+: C224.1 D68.1(I/O2) J37.3(R)
MIC1_IN: D65.1(I/O2) J36.1 R388.2
MIC2_IN: D69.1(I/O2) J37.1(GND) R387.2
PDM_CLK0_M0: J45.3 R308.2
PDM_SDI1_M0: J45.5 R311.2
PDM_SDI2_M0: J45.4 R310.2
SPK_CTL_H: R454.1 R1201.1 ; port SPK_EN_H_GPIO4_B6_d
SPK_CTL_L: Q5.3(DRAIN) U25.5(~{MUTE}) U25.12(~{SD})  [also labelled SPK_MUTE_L]
VOLN: C216.1 J35.1 L25.2
VOLP: C217.1 J35.2 L26.2
VORN: C220.1 J35.3 L27.2
VORP: C221.1 J35.4 L28.2
NetC214_2: C214.2 U25.8(Bypass)
NetC215_2: C215.2 R303.1
NetC219_2: C219.2 R309.1
NetC223_2: C223.2 D67.1(I/O2) J37.5(L-COM) R314.1 R455.2
NetC280_2: C280.2 R387.1 R466.2
NetC281_2: C281.2 R388.1 R465.2
NetL25_1: L25.1 U25.3(VOLN)
NetL26_1: L26.1 U25.1(VOLP)
NetL27_1: L27.1 U25.14(VORN)
NetL28_1: L28.1 U25.16(VORP)
NetM1_72: R308.1 ; port PCIE20_CLKREQN_M1
NetM1_73: R310.1 ; port PCIE20_WAKEN_M1
NetM1_74: R311.1 ; port PCIE20_PERSTN_M1
NetQ5_1: Q5.1(GATE) R446.1 R454.2
NetR303_2: R303.2 U25.7(INL)
NetR309_2: R309.2 U25.10(INR)

Not connected (* = marked no-connect by the designer): J37 6(R-COM)*; J45 2

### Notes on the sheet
- MIC_IN
- Speaker Output(Stereo)
- Ground Guard
- Connect HP_SNS to Ground at Audio Jack side
- HPR_OUT
- HP_SNS
- HPL_OUT
- Audio
  Jack
- Place 0ohm resister close to GND pin of Headphone Jack ,
  at layout,HP_SNS walks in the middle of HPL/HPR
  and acts as an accompanying line to avoid interference.

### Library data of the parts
C207 = C-0402_Dup2: Part Number: C020102120064; Part Name: 贴片电容; Manufacture: 三星¦国巨¦村田; ERP Number: 1010200054; DSC1: ±10%; DSC3: X5R; ID: 64; PCB Footprint: C0402
C208 C209 C215 C219 = C-0402_Dup1: Part Number: C020102120061; Part Name: 贴片电容; Manufacture: 三星¦国巨¦村田; ERP Number: 1010200128; DSC1: ±10%; DSC3: X7R; ID: 61; PCB Footprint: C0402
C210-C212 = C-0805_Dup1: Part Number: C020102120075; Part Name: 贴片电容; Manufacture: 三星¦国巨¦村田; DSC1: ±20%; DSC3: X5R; ID: 75; PCB Footprint: C0805
C213 = C-0805_Dup1: Manufacture: 三星¦国巨¦村田; Part Name: 贴片电容; Part Number: C020102120075; ID: 75; DSC3: X5R; DSC1: ±20%; PCB Footprint: C0805
C214 = C-0402_Dup2: Manufacture: 三星¦国巨¦村田; Part Name: 贴片电容; Part Number: C020102120064; ID: 64; DSC3: X5R; DSC1: ±10%; ERP Number: 1010200054; PCB Footprint: C0402
C216 C217 C220 C221 = C-0402_Dup2: Manufacture: 三星¦国巨¦村田; Part Name: 贴片电容; Part Number: C020102120054; ID: 54; DSC3: X7R; DSC1: ±10%; ERP Number: 1010200084; PCB Footprint: C0402
C222 C224 C226 C227 = C-0603: as C46 on sheet P21. USB3
C223 = C-0402_Dup2: as C348-C352 on sheet P21. USB3
C280 C281 = C-0603: as C262 on sheet P21. USB3
D65 D67-D69 = DI-ESD: as D9 on sheet P21. USB3
D66 = DI-ESD: as D8 on sheet P21. USB3
J35 = J-H-4P: Part Number: J020302820003; Part Name: PH; DSC1: 4p; DSC2: 2.0mm间距; DSC3: 通孔180度直针; DSC4: 米黄色胶壳 耐高温; DSC5: JLX-PH20-4A（九龙熹）; DSC6: X2016WV-04-46SN(星坤); ID: 13
J36 = J-A-2P: Part Number: J020102800058; DSC1: 2p; DSC2: 1.25mm间距; DSC3: 立贴; DSC4: 米黄色胶壳 耐高温; DSC5: JLX-1.25T-2AB(九龙熹); DSC6: X9821WVS-02-9TSN(星坤); ID: 6
J37 = J-PJ-316A-6A: Part Name: 音频耳机座; Part Number: J050502940002; ID: 10; DSC5: PJ-31160（九龙熹）; DSC4: PJ-316A-6A(韩荣); DSC2: 14*6*4mm; DSC1: 3.5mm贴片式耳机座 凸头 6P 单定位柱
J45 = J-FPC-6P: Part Number: J030102870207; Part Name: FPC座; DSC1: 6P; DSC2: 1mm间距; DSC3: 下接 翻盖 卧贴; DSC4: H=2mm; DSC5: 镀锡; DSC6: X10A20L06T（星坤）; ID: 23
L25-L28 = FB-0603: SMD Multilayer Ferrite Chip Bead,3A,30Ohm,0.03R; Part Number: C060502370005; Manufacture P/N: PZ1608D300-3R0TF; Manufacture2 P/N: PBY160808T-400Y-N; Manufacturer: SUNLORD; Part Name: 贴片磁珠; Manufacture: 顺络; PN Type: SMD FERRITE BEAD; ERP Number: 1010200207; DSC1: 100Ω@100MHz; DSC3: DCR=30mΩ; DSC4: 电源线; ID: 5
Q5 = N-MOS-Q: Manufacture: 先科; Part Name: N-MOS; Part Number: C030202190004; ID: 4; DSC5: pd=150mW; DSC4: Vgs=±20V; DSC3: Vgs(th)=1.5V; DSC2: Id=100mA; DSC1: Vds=30V; ERP Number: 1010800011
R299 = R-0603_Dup1: Part Name: 贴片电阻; Part Number: C011002081182; ERP Number: 1010200158; DSC1: ±1%; DSC2: 1/10W; ID: 1,182
R300 R318 = R-0603_Dup1: Part Number: C011002081182; Part Name: 贴片电阻; ID: 1,182; DSC2: 1/10W; DSC1: ±1%; ERP Number: 1010200158
R303 R309 = R-0402_Dup1: Part Name: 贴片电阻; Part Number: C011002080335; DSC1: ±5%; DSC2: 1/16W; ID: 335
R306 R308 R310 R311 = R-0402_Dup3: as R352 on sheet P21. USB3
R314 = R-0402_Dup3: Part Number: C011002080353; Part Name: 贴片电阻; ID: 353; DSC2: 1/16W; DSC1: ±5%; ERP Number: 1010200103
R316 = R-0402_Dup3: as R258-R260 on sheet P21. USB3
R387 R388 = R-0402_Dup3: Part Number: C011002080778; Part Name: 贴片电阻; ID: 778; DSC2: 1/16W; DSC1: ±1%
R446 R1201 = R-0402_Dup3: as R445 on sheet P21. USB3
R447 = R-0402_Dup3: Part Name: 贴片电阻; Part Number: C011002080856; ERP Number: 1010200140; DSC1: ±1%; DSC2: 1/16W; ID: 856
R454 R455 = R-0402_Dup3: Part Number: C011002080742; Part Name: 贴片电阻; ID: 742; DSC2: 1/16W; DSC1: ±1%; ERP Number: 1010200113
R465 R466 = R-0402_Dup3: as R264 on sheet P22
U25 = U-NS4205: Manufacture: Nsiway(纳芯威); Part Number: C150102670002; Part Name: 功放; ID: 2; DSC3: -40~85℃; DSC1: 2*3W @4Ω,3~5.2V，Class D; ERP Number: 1010100190

## Sheet P30.SchDoc
size 297 x 209 mm
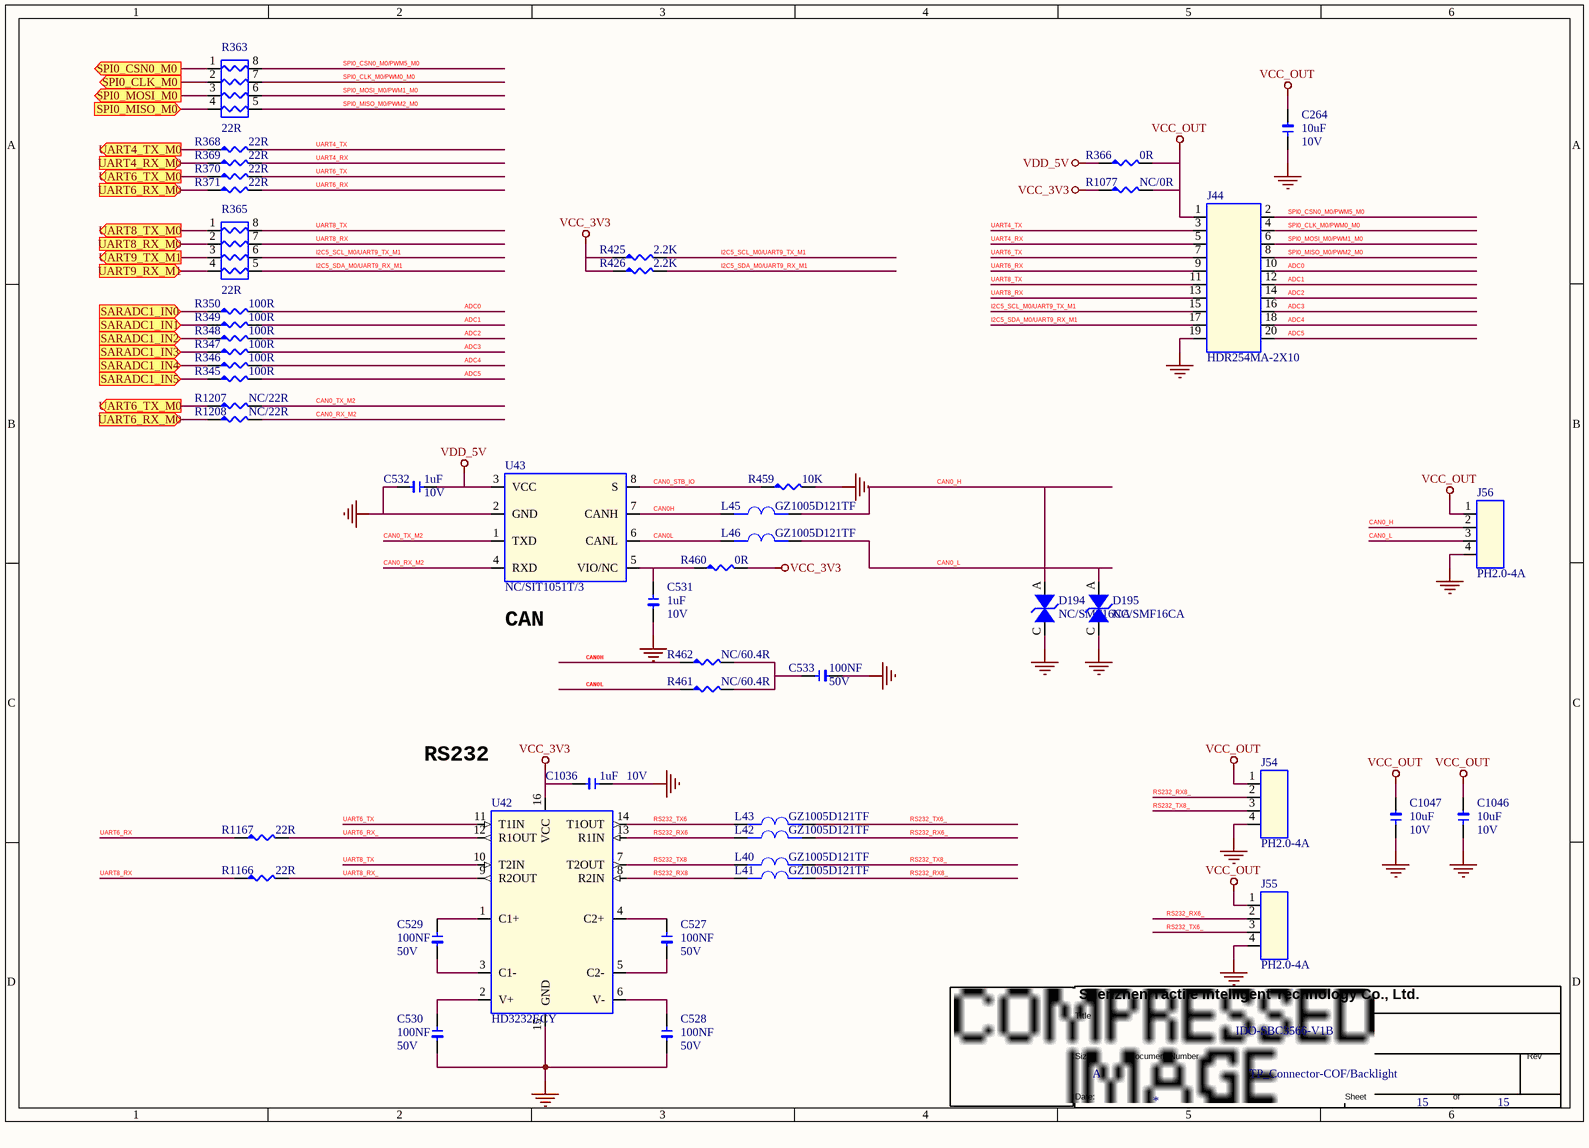
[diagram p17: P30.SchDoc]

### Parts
(Parts that share a designator on the sheet are numbered #1, #2 ... from top to bottom, then left to right.)
*#11  Page Count: 15  Page Size: A  Title: IDO-SBC3566-V1B  Doc: TP_Connector-COF/Backlight  (hidden comment: TitleBlock1)  (graphical)
C264  10uF  DSC2: 10V  [1206]
C527  100NF  DSC2: 50V  [1206]
C528  100NF  DSC2: 50V  [1206]
C529  100NF  DSC2: 50V  [1206]
C530  100NF  DSC2: 50V  [1206]
C531  1uF  DSC2: 10V  [1206]
C532  1uF  DSC2: 10V  [1206]
C533  100NF  DSC2: 50V  [1206]
C1036  1uF  DSC2: 10V  [1206]
C1046  10uF  DSC2: 10V  [1206]
C1047  10uF  DSC2: 10V  [1206]
D194  NC/SMF16CA  [SOD-123F]
D195  NC/SMF16CA  [SOD-123F]
J44  HDR254MA-2X10  [HDR254MA-2X10]
J54  PH2.0-4A  [PH200-4A]
J55  PH2.0-4A  [PH200-4A]
J56  PH2.0-4A  [PH200-4A]
L40  GZ1005D121TF  [L0402]
L41  GZ1005D121TF  [L0402]
L42  GZ1005D121TF  [L0402]
L43  GZ1005D121TF  [L0402]
L45  GZ1005D121TF  [L0402]
L46  GZ1005D121TF  [L0402]
R345  100R  [R0402]
R346  100R  [R0402]
R347  100R  [R0402]
R348  100R  [R0402]
R349  100R  [R0402]
R350  100R  [R0402]
R363  22R  [RN_0402X4]
R365  22R  [RN_0402X4]
R366  0R  [R0402]
R368  22R  [R0402]
R369  22R  [R0402]
R370  22R  [R0402]
R371  22R  [R0402]
R425  2.2K  [R0402]
R426  2.2K  [R0402]
R459  10K  [R0402]
R460  0R  [R0402]
R461  NC/60.4R  [R0603]
R462  NC/60.4R  [R0603]
R1077  NC/0R  [R0402]
R1166  22R  [R0402]
R1167  22R  [R0402]
R1207  NC/22R  [R0402]
R1208  NC/22R  [R0402]
U42  HD3232ECY  [TSSOP-16]
U43  NC/SIT1051T/3  [SOP8-P127-390X490]

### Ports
SARADC1_IN0 (in), SARADC1_IN1 (in), SARADC1_IN2 (in), SARADC1_IN3 (in), SARADC1_IN4 (in), SARADC1_IN5 (in), SPI0_CLK_M0 (out), SPI0_CSN0_M0 (out), SPI0_MISO_M0 (in), SPI0_MOSI_M0 (out), UART4_RX_M0 (in), UART4_TX_M0 (out), UART6_RX_M0 (in), UART6_TX_M0 (out), UART8_RX_M0 (in), UART8_TX_M0 (out), UART9_RX_M1 (in), UART9_TX_M1 (out)

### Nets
GND: C264.1 C528.2 C530.2 C531.2 C532.2 C533.2 C1036.1 C1046.1 C1047.1 D194.C(I/O1) D195.C(I/O1) J44.19 J54.4 J55.4 J56.4 R459.2 U42.15(GND) U43.2(GND)
VCC_3V3: C1036.2 R425.1 R426.1 R460.2 R1077.1 U42.16(VCC)
VCC_OUT: C264.2 C1046.2 C1047.2 J44.1 J54.1 J55.1 J56.1 R366.2 R1077.2
VDD_5V: C532.1 R366.1 U43.3(VCC)
ADC0: J44.10 R350.2
ADC1: J44.12 R349.2
ADC2: J44.14 R348.2
ADC3: J44.16 R347.2
ADC4: J44.18 R346.2
ADC5: J44.20 R345.2
CAN0_H: D194.A(I/O2) J56.2 L45.2
CAN0_L: D195.A(I/O2) J56.3 L46.2
CAN0_RX_M2: R1208.2 U43.4(RXD)
CAN0_STB_IO: R459.1 U43.8(S)
CAN0_TX_M2: R1207.2 U43.1(TXD)
CAN0H: L45.1 R462.1 U43.7(CANH)
CAN0L: L46.1 R461.1 U43.6(CANL)
I2C5_SCL_M0/UART9_TX_M1: J44.15 R365.6 R425.2
I2C5_SDA_M0/UART9_RX_M1: J44.17 R365.5 R426.2
RS232_RX6: L42.1 U42.13(R1IN)
RS232_RX6_: J55.2 L42.2
RS232_RX8: L41.1 U42.8(R2IN)
RS232_RX8_: J54.2 L41.2
RS232_TX6: L43.1 U42.14(T1OUT)
RS232_TX6_: J55.3 L43.2
RS232_TX8: L40.1 U42.7(T2OUT)
RS232_TX8_: J54.3 L40.2
SPI0_CLK_M0/PWM0_M0: J44.4 R363.7
SPI0_CSN0_M0/PWM5_M0: J44.2 R363.8
SPI0_MISO_M0/PWM2_M0: J44.8 R363.5
SPI0_MOSI_M0/PWM1_M0: J44.6 R363.6
UART4_RX: J44.5 R369.2
UART4_TX: J44.3 R368.2
UART6_RX: J44.9 R371.2 R1167.1
UART6_RX_: R1167.2 U42.12(R1OUT)
UART6_TX: J44.7 R370.2 U42.11(T1IN)
UART8_RX: J44.13 R365.7 R1166.1
UART8_RX_: R1166.2 U42.9(R2OUT)
UART8_TX: J44.11 R365.8 U42.10(T2IN)
NetC272_2: R350.1 ; port SARADC1_IN0
NetC273_2: R349.1 ; port SARADC1_IN1
NetC274_2: R348.1 ; port SARADC1_IN2
NetC275_2: R347.1 ; port SARADC1_IN3
NetC276_2: R346.1 ; port SARADC1_IN4
NetC277_2: R345.1 ; port SARADC1_IN5
NetC527_1: C527.1 U42.4(C2+)
NetC527_2: C527.2 U42.5(C2-)
NetC528_1: C528.1 U42.6(V-)
NetC529_1: C529.1 U42.1(C1+)
NetC529_2: C529.2 U42.3(C1-)
NetC530_1: C530.1 U42.2(V+)
NetC531_1: C531.1 R460.1 U43.5(VIO/NC)
NetC533_1: C533.1 R461.2 R462.2
NetM1_77: R365.4 ; port UART9_RX_M1
NetM1_78: R365.3 ; port UART9_TX_M1
NetM1_85: R365.2 ; port UART8_RX_M0
NetM1_86: R365.1 ; port UART8_TX_M0
NetM1_91: R368.1 ; port UART4_TX_M0
NetM1_92: R369.1 ; port UART4_RX_M0
NetM1_159: R363.1 ; port SPI0_CSN0_M0
NetM1_160: R363.2 ; port SPI0_CLK_M0
NetM1_161: R363.3 ; port SPI0_MOSI_M0
NetM1_162: R363.4 ; port SPI0_MISO_M0
NetM1_163: R370.1 R1207.1 ; port UART6_TX_M0
NetM1_164: R371.1 R1208.1 ; port UART6_RX_M0

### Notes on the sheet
- (near U43) CAN
- (near U42) RS232

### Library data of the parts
C264 = C-0603: as C45 on sheet P21. USB3
C527-C530 C533 = C-0402_Dup2: as C347 on sheet P21. USB3
C531 C532 = C-0402_Dup2: as C214 on sheet P24
C1036 = C-0402_Dup1: as C1038 on sheet P21. USB3
C1046 = C-0603: as C262 on sheet P21. USB3
C1047 = C-0603: as C46 on sheet P21. USB3
D194 D195 = DI-TVS-D: ESD 0402; Manufacturer: INPAQ; Manufacture P/N: MLVG04021R0UV18; Part Number: EB3.1R0UV18402A; Part Name: TVS; Manufacture: 硕凯; PN Type: Varistor; DSC1: 双向; DSC2: Vrwm=16V; DSC3: VBR=17.8V; DSC4: Vc=26V; DSC5: Ipp=15.4A; DSC6: Ppp=200W; ID: 28
J44 = J-HDR-D-20: Part Name: 双排针; Part Number: J010102760104; ID: 51; DSC7: X6521WV-2x10H-C30D60（星坤）; DSC6: 黑胶; DSC5: 针长11.5mm 3+2.5(H塑高)+6mm; DSC4: 通孔直针; DSC3: 2.54mm脚距; DSC2: 2x10; DSC1: 双排单塑
J54 = J-H-4P: Part Name: PH; Part Number: J020302820003; ID: 13; DSC6: X2016WV-04-46SN(星坤); DSC5: JLX-PH20-4A（九龙熹）; DSC4: 米黄色胶壳 耐高温; DSC3: 通孔180度直针; DSC2: 2.0mm间距; DSC1: 4p
J55 J56 = J-H-4P: as J35 on sheet P24
L40-L43 = FB-0402: SMD Multilayer Ferrite Chip Bead,3A,30Ohm,0.03R; Manufacturer: SUNLORD; Manufacture2 P/N: PBY160808T-400Y-N; Manufacture P/N: PZ1608D300-3R0TF; Part Number: C060502370001; Manufacture: 顺络; Part Name: 贴片磁珠; PN Type: SMD FERRITE BEAD; ID: 1; DSC4: 低频信号; DSC3: DCR=400mΩ; DSC2: 200mA; DSC1: 120Ω@100MHz; ERP Number: 1010200208
L45 L46 = FB-0402: SMD Multilayer Ferrite Chip Bead,3A,30Ohm,0.03R; Manufacturer: SUNLORD; Manufacture2 P/N: PBY160808T-400Y-N; Manufacture P/N: PZ1608D300-3R0TF; Part Number: C060502370001; Part Name: 贴片磁珠; Manufacture: 顺络; PN Type: SMD FERRITE BEAD; ERP Number: 1010200208; DSC1: 120Ω@100MHz; DSC2: 200mA; DSC3: DCR=400mΩ; DSC4: 低频信号; ID: 1
R345-R350 = R-0402_Dup3: as R264 on sheet P22
R363 = RN_0402X4: Part Name: 贴片排阻; Part Number: C010302090004; ID: 4; DSC1: ±5%; DSC2: 1/16W
R365 = RN_0402X4: Part Number: C010302090004; Part Name: 贴片排阻; DSC2: 1/16W; DSC1: ±5%; ID: 4
R366 = R-0402_Dup3: as R258-R260 on sheet P21. USB3
R368-R371 = R-0402_Dup3: as R1171 on sheet P21. USB3
R425 R426 = R-0402_Dup3: as R387 on sheet P24
R459 = R-0402_Dup1: Part Name: 贴片电阻; Part Number: C011002080328; ERP Number: 1010200096; DSC1: ±5%; DSC2: 1/16W; ID: 328
R460 = R-0402_Dup1: Part Number: C011002080217; Part Name: 贴片电阻; ID: 217; DSC2: 1/16W; DSC1: ±5%; ERP Number: 1010200100
R461 = R-0603: Part Name: 贴片电阻; Part Number: C011002081339; DSC1: ±1%; DSC2: 1/10W; ID: 1,339
R462 = R-0603: Part Number: C011002081339; Part Name: 贴片电阻; ID: 1,339; DSC2: 1/10W; DSC1: ±1%
R1077 = R-0402_Dup3: as R352 on sheet P21. USB3
R1166 R1167 = R-0402_Dup3: Part Name: 贴片电阻; Part Number: C011002080552; DSC1: ±1%; DSC2: 1/16W; ID: 552
R1207 R1208 = R-0402_Dup3: as R344 on sheet P22
U42 = U-SP3232EEN: Part Number: C100305124693; Part Name: RS232/RS485芯片; Manufacture: Broadic; DSC1: RS232 Transceiver up to 235kbps; DSC2: TSSOP-16，0.65mm Pitch; DSC3: -40℃~+85℃; ID: 73
U43 = U-TJA1057GT-3J: Part Number: C100405124698; Part Name: CAN芯片; Manufacture: 芯力特; DSC1: CAN Transceiver, 5Mbps; DSC2: SOIC-8_150mil，1.27mm Pitch; DSC3: -40℃~+85℃; ID: 76

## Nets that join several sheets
GND: P11 (40 pins), P12 (59 pins), P13 (39 pins), P14 (42 pins), P15 (41 pins), P16 (79 pins), P17 (24 pins), P18 (38 pins), P19 (29 pins), P20 (27 pins), P21. USB3 (66 pins), P22 (19 pins), P24 (36 pins), P30 (18 pins)
GND_EARTH: P12 (Hole5.1 Hole9.1 Hole10.1 Hole11.1), P17 (J21.SH1 J21.SH2), P18 (J22.SH1 J22.SH2), P19 (J23.13 J23.14)
VCC3V3_SYS: P11 (12 pins), P12 (R431.1), P15 (C284.1 R62.1 R423.1 U59.11), P20 (6 pins), P22 (D48.A)
VCC5V_SYS: P11 (17 pins), P12 (R17.2 R1209.2 R1210.2), P13 (6 pins), P14 (C77.2 C316.2 U9.4), P21. USB3 (9 pins)
VCC_1V8_OUT: P11 (R1078.1), P12 (6 pins), P15 (5 pins)
VCC_3V3: P11 (C1033.2 Q10.3 R1084.2), P12 (R19.1 R415.1), P13 (R48.2 R437.2), P15 (C91.2 J15.5 J46.19 J46.20), P16 (13 pins), P17 (R160.1), P18 (R194.1), P19 (L12.1), P22 (R261.2), P24 (7 pins), P30 (6 pins)
VCC_DCIN: P11 (F3.1 F4.1 J1.4), P15 (J15.1 J43.5 J43.6)
VDD_5V: P11 (C1011.2 Q8.3), P15 (5 pins), P24 (C213.2 R300.2), P30 (C532.1 R366.1 U43.3)
4G_POWER_H: P12 (M1.108), P14 (R441.1)
HP_DET_L: P12 (M1.153), P24 (R455.1)
HUB_HOST3_PWREN_H: P12 (R430.1), P13 (R450.1 U4.4)
HUB_HOST4_PWREN_H: P12 (R1082.1), P13 (R451.1 U5.4)
LCD_TX_CLKN: P12 (M1.147), P15 (D21.4 D21.7 J16.15 R1186.1)
LCD_TX_CLKP: P12 (M1.146), P15 (D21.5 D21.6 J16.16 R1187.1)
LCD_TX_D0N: P12 (M1.151), P15 (D20.1 D20.10 J16.7 R1182.1)
LCD_TX_D0P: P12 (M1.150), P15 (D20.2 D20.9 J16.8 R1183.1)
LCD_TX_D1N: P12 (M1.149), P15 (D20.4 D20.7 J16.9 R1184.1)
LCD_TX_D1P: P12 (M1.148), P15 (D20.5 D20.6 J16.10 R1185.1)
LCD_TX_D2N: P12 (M1.145), P15 (D21.1 D21.10 J16.11 R1188.1)
LCD_TX_D2P: P12 (M1.144), P15 (D21.2 D21.9 J16.12 R1189.1)
LCD_TX_D3N: P12 (M1.143), P15 (D24.2 D24.9 J16.17 R1190.1)
LCD_TX_D3P: P12 (M1.142), P15 (D24.1 D24.10 J16.18 R1191.1)
MIPI_RST: P12 (R78.1), P15 (C93.2 J46.16 R444.1)
NetC155_2: P12 (M1.36), P19 (C155.2 R213.1)
NetC272_2: P12 (C272.2 M1.62), P30 (R350.1)
NetC273_2: P12 (C273.2 M1.63), P30 (R349.1)
NetC274_2: P12 (C274.2 M1.64), P30 (R348.1)
NetC275_2: P12 (C275.2 M1.65), P30 (R347.1)
NetC276_2: P12 (C276.2 M1.66), P30 (R346.1)
NetC277_2: P12 (C277.2 M1.67), P30 (R345.1)
NetM1_6: P12 (M1.6), P13 (R36.1)
NetM1_8: P11 (R4.1 R9.1), P12 (M1.8), P21. USB3 (R1171.1)
NetM1_15: P11 (R1083.1), P12 (M1.15)
NetM1_16: P12 (M1.16 R391.1), P21. USB3 (R342.1)
NetM1_28: P12 (M1.28), P17 (R403.1)
NetM1_29: P12 (M1.29), P17 (R404.1)
NetM1_32: P12 (M1.32), P19 (R208.1)
NetM1_33: P12 (M1.33), P19 (R210.1)
NetM1_38: P12 (M1.38), P19 (R201.1)
NetM1_39: P12 (M1.39), P19 (R198.1)
NetM1_40: P12 (M1.40), P19 (R199.1)
NetM1_41: P12 (M1.41), P19 (R202.1)
NetM1_42: P12 (M1.42), P19 (R203.1)
NetM1_72: P12 (M1.72), P17 (R155.1), P21. USB3 (R258.1), P24 (R308.1)
NetM1_73: P12 (M1.73), P17 (R154.1), P21. USB3 (R259.1), P24 (R310.1)
NetM1_74: P12 (M1.74), P17 (R153.1), P21. USB3 (R260.1), P24 (R311.1)
NetM1_77: P12 (M1.77), P30 (R365.4)
NetM1_78: P12 (M1.78), P30 (R365.3)
NetM1_83: P12 (M1.83), P16 (R1180.1)
NetM1_84: P12 (M1.84), P16 (R1179.1)
NetM1_85: P12 (M1.85), P30 (R365.2)
NetM1_86: P12 (M1.86), P30 (R365.1)
NetM1_87: P12 (M1.87), P16 (R1172.1)
NetM1_88: P12 (M1.88), P16 (R372.1)
NetM1_89: P12 (M1.89), P16 (R124.1)
NetM1_90: P12 (M1.90), P16 (R125.1)
NetM1_91: P12 (M1.91), P30 (R368.1)
NetM1_92: P12 (M1.92), P30 (R369.1)
NetM1_93: P12 (M1.93), P16 (R126.1)
NetM1_94: P12 (M1.94), P16 (R127.1)
NetM1_109: P12 (M1.109), P16 (R123.1)
NetM1_112: P12 (M1.112), P16 (R128.1)
NetM1_113: P12 (M1.113), P16 (R129.1)
NetM1_154: P12 (M1.154), P15 (R98.1)
NetM1_157: P12 (M1.157), P15 (R75.1 R99.1)
NetM1_158: P12 (M1.158), P21. USB3 (R353.1)
NetM1_159: P12 (M1.159), P30 (R363.1)
NetM1_160: P12 (M1.160), P30 (R363.2)
NetM1_161: P12 (M1.161), P30 (R363.3)
NetM1_162: P12 (M1.162), P30 (R363.4)
NetM1_163: P12 (M1.163), P30 (R370.1 R1207.1)
NetM1_164: P12 (M1.164), P30 (R371.1 R1208.1)
NetR352_1: P12 (R429.1), P21. USB3 (R352.1)
RMII_RXD0: P12 (M1.37), P19 (R197.2)
RMII_RXD1: P12 (M1.34), P19 (R196.2)
RMII_RXDV: P12 (M1.35), P19 (R215.1 R1198.2)
SCL_TP: P12 (M1.71), P15 (U59.9), P22 (R343.1)
SDA_TP: P12 (M1.70), P15 (U59.10), P22 (R344.1)
SPK_CTL_H: P12 (M1.114), P24 (R454.1 R1201.1)
TP_INT_L: P12 (M1.156), P15 (U59.8)
TP_RST_L: P12 (M1.155), P15 (U59.7)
